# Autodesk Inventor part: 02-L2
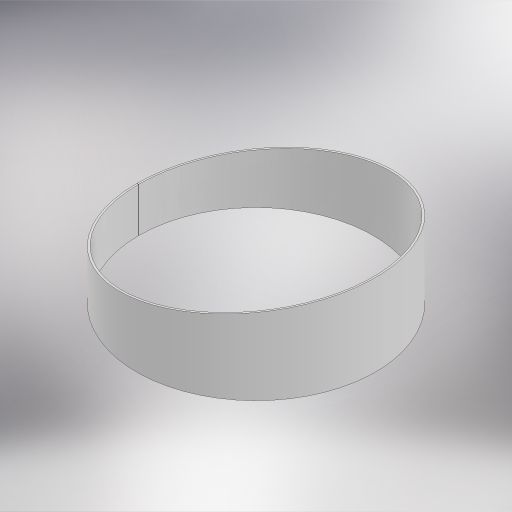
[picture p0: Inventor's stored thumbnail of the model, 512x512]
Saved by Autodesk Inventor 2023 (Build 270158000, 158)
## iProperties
Created: 2023-01
Part Number: 02-L2
Material: Generic
Document SubType Name: Sheet Metal
Designer: Nelson C Agudelo A
Density: 1 g/cm^3
Flat Pattern Width: 10.295 cm
Flat Pattern Length: 93.3582 cm
Flat Pattern Area: 961.122 cm^2
Sheet Metal Rule: Default_mm
Sheet Metal Width: 102,950 mm
Sheet Metal Length: 933,582 mm
Sheet Metal Area: 96112,188 mm^2
Appearance: Default
Author: Nelson C Agudelo A
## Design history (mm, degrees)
derived "01-Esquema Codo Mitrado.ipt"
  sketch "Sketch1"
    geometry: L1 (0, 0)-(500, 0) reference; L2 (500, 0)-(500, 79.192) reference; L3 (350, 0)-(350, 55.435) reference; L4 (650, 0)-(650, 102.95) reference; L5 (0, 0)-(650, 102.95) reference; L6 (0, 0)-(-500, 0) reference; L7 (-350, 0)-(-350, 55.435) reference; L8 (-650, 0)-(-650, 102.95) reference; L9 (-500, 0)-(-650, 0) reference; L10 (0, 0)-(-650, 102.95) reference; L11 (-500, 0)-(-500, 79.192) reference; L12 (0, 0)-(451.057, 229.825) reference; L13 (500, 79.192)-(451.057, 229.825) reference; L14 (0, 0)-(475.528, 154.508) reference; L15 (650, 0)-(1150, 0) reference; L16 (500, 0)-(1000, 0) reference; L17 (1000, 0)-(1500, 0) reference; 1 further point
node "Contour Flange1"
  sketch "Sketch2"
    geometry: L1 (-500, 0)-(-350, -0.05); L2 (-500, 0)-(-350, 0.05); L3 (-350, -0.05)-(-350, 0.05); A1 r 150 centre (-500, 0) between (-350, 0) and (-350, 0.05); A2 r 150 centre (-500, 0) between (-350, 0.05) and (-350, -0.05); 2 further points
    constraints: 6 end point, 4 point on circle, 2 centre point, 1 coincident, 1 midpoint, 1 vertical
    dimensions: "d7" = 300 diameter of A1 (= ODtuberia); "d10" = 0.1 distance of L1.end L2.end
sketch "Sketch3"
  geometry: L1 (0, 0)-(650, 102.95); L2 (650, 102.95)-(650, 0) reference; L3 (0, 0)-(650, 191.193); L4 (650, 102.95)-(350, 102.95) reference; L5 (650, 191.193)-(650, 102.95)
  constraints: 6 end point, 2 point on line, 1 collinear
cut "Cut1" sketch "Sketch3" dims "d24" = 2.5 (= Thickness), "d25" = 0
body "Solid1"
face "Plate1" dims "d11" = 2.5 (= Thickness), "d12" = 2.5 (= BendReliefWidth), "d15" = 1.25 (= BendReliefDepth), "d16" = 5 (= MinimumRemnant), "d17" = 2.5 (= TransitionRadius), "d18" = 102.94989 (= L2 + Recorte), "d19" = 2.5 (= BendRadius), "d20" = 2.5, "d21" = 10 (= CornerReliefSize), "d22" = 2.5 (= GapSize), "d23" = 2.5 (= JacobiRadiusSize), "SeamGap" = 0.01
bend "Bend1" dims "d11" = 2.5 (= Thickness), "d12" = 2.5 (= BendReliefWidth), "d15" = 1.25 (= BendReliefDepth), "d16" = 5 (= MinimumRemnant), "d17" = 2.5 (= TransitionRadius), "d19" = 2.5 (= BendRadius), "d20" = 2.5, "SeamGap" = 0.01
feature "Corner1" dims "d20" = 2.5, "d21" = 10 (= CornerReliefSize), "d22" = 2.5 (= GapSize), "d23" = 2.5 (= JacobiRadiusSize)
feature "Definition1"
other parameters: "Thickness" = 2.5 (derived), "BendRadius" = 2.5 (= Thickness), "BendReliefWidth" = 2.5 (= Thickness), "BendReliefDepth" = 1.25 (= 0.5 x Thickness), "MinimumRemnant" = 5 (= 2 x Thickness), "TransitionRadius" = 2.5 (= BendRadius), "JacobiRadiusSize" = 2.5 (= BendRadius), "GapSize" = 2.5 (= Thickness), "d2" = 79.19222, "d3" = 180 deg, "DL1" = 18 deg, "d13" = 158.38444, "L2" = 79.19222, "L1" = 158.38444, "Recorte" = 23.75767, "D" = 180 deg, "ODtuberia" = 300, "DL2" = 9 deg, "d14" = 23.75767, "BendRadius" = 2.5, "BendReliefDepth" = 1.25, "BendReliefWidth" = 2.5, "D" = 180 deg, "DL1" = 18 deg, "DL2" = 9 deg, "GapSize" = 2.5, "JacobiRadiusSize" = 2.5, "L1" = 158.38444, "L2" = 79.19222, "MinimumRemnant" = 5, "Recorte" = 23.75767, "Thickness" = 2.5, "TransitionRadius" = 2.5
